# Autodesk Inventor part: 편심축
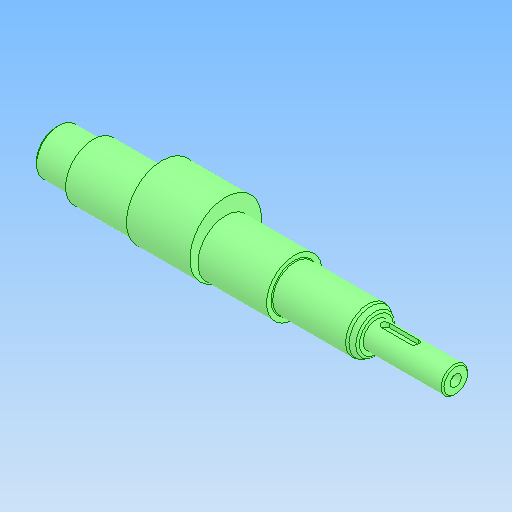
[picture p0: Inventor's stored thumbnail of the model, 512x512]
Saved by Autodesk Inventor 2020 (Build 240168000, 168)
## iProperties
Created: 2024-09
Part Number: 편심축
Material: 강철, 탄소
Document SubType Name: Modeling
Designer: oem
Density: 7.85 g/cm^3
Appearance: 기본값
Author: jhkim
Sending System: Autodesk Inventor 2025
Preprocessor: ST-DEVELOPER v20
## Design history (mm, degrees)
feature "솔리드1"
node "솔리드2"
